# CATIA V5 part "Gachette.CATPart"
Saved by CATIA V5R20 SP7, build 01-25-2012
Part number: Gachette
Bounding box of the stored display mesh (mm): x -7.388 to 7.388, y 0 to 54, z -7.49 to 7.49
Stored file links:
  F:\Travaux\Modélisations\CFAO_2011\MMS\MMS_GR1\AA_OK\bmadec\Catia\Gachette.CATPart
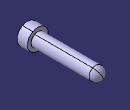
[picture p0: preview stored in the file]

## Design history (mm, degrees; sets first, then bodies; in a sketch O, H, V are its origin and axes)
Body1 (main body)
  Sketch1 on yz-plane, origin (0, 0, 0), H (0, 1, 0), V (0, 0, 1)
    point P1 (0, 0)
    line L1 (0, 0) -> (0, 7.5)
    line L2 (0, 7.5) -> (7.5, 7.5)
    line L3 (7.5, 7.5) -> (7.5, 4.875)
    line L4 (7.5, 4.875) -> (49.125, 4.875)
    arc A1 centre (49.125, 0) radius 4.875 from (49.125, 4.875) to (54, 0) cw
    point P6 (49.125, 0)
    point P7 (54, 0)
    line L5 (54, 0) -> (0, 0)
    radius A1 = 4.875
    length L1 = 7.5
    length L5 = 54
    length L2 = 7.5
    coincidence: P1 H, P7 H, P6 L5, P1 O
    vertical: L1 V, L3 V
    horizontal: L2 H, L4 H, L5 H
    tangency: A1 L4
  Shaft1: profile Sketch1, axis Sketch1.L5, angle 360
